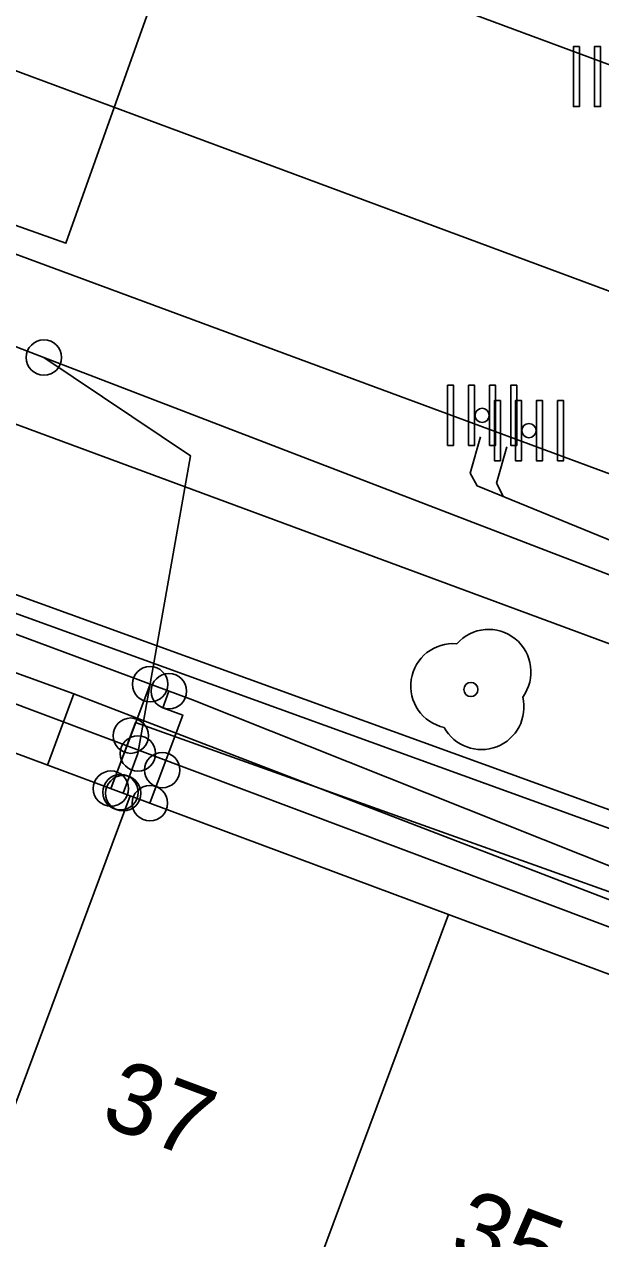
# Model space of a CAD drawing. Extents: x 192672 to 192910, y 446344 to 446512.
# Drawn here: x 192717.1 to 192725.25, y 446389.57 to 446406.75 of the extents above; entities that cross this region are included whole.
import ezdxf

# ---------------------------------------------------------------- set-up
doc = ezdxf.new("R2010")
doc.units = 0
for name, color, linetype in [('B-OI-KL-BUISLEIDING_OLIEGASCHEMICALIEN_GASLAGEDRUK-G', 7, 'Continuous'), ('B-OI-KL-DATA-G', 7, 'Continuous'), ('B-OI-KL-DATA_GTWP-S', 7, 'Continuous'), ('B-OI-KL-DATA_KABELBED-G', 7, 'Continuous'), ('B-OI-KL-DATA_MOF-S', 7, 'Continuous'), ('B-OI-KL-ET_LS-G', 7, 'Continuous'), ('B-OI-KL-ET_LS_DELIVERYPOINT-S', 7, 'Continuous'), ('B-OI-KL-GAS_LD_AFTAKZADEL-S', 7, 'Continuous'), ('B-OI-KL-GAS_LD_DELIVERYPOINT-S', 7, 'Continuous'), ('B-OI-KL-GAS_LD_OVERGANGSSTUK-S', 7, 'Continuous'), ('B-OI-KL-WATER-G', 7, 'Continuous'), ('B-OI-RI-RIOOLVRIJVERVAL-G', 7, 'Continuous'), ('boom', 7, 'Continuous'), ('Default', 7, 'Continuous'), ('huisnummerreeks BGT', 7, 'Continuous'), ('kant open verharding', 7, 'Continuous'), ('kant verharding', 7, 'Continuous'), ('kolk', 7, 'Continuous'), ('pand op maaiveld vlak', 7, 'Continuous'), ('verkeerseiland - berm', 7, 'Continuous')]:
    doc.layers.add(name, color=color, linetype=linetype)

# ---------------------------------------------------------------- blocks, each defined once
blk = doc.blocks.new('B-OI-KL-GAS_LD_AFTAKZADEL-S')
at = {"layer": 'Default'}
blk.add_circle((0, 0), 0.25, dxfattribs=at)
blk = doc.blocks.new('B-OI-KL-GAS_LD_DELIVERYPOINT-S')
at = {"layer": 'Default'}
blk.add_circle((0, 0), 0.25, dxfattribs=at)
blk = doc.blocks.new('B-OI-KL-GAS_LD_OVERGANGSSTUK-S')
at = {"layer": 'Default'}
blk.add_circle((0, 0), 0.25, dxfattribs=at)
blk = doc.blocks.new('B-OI-KL-ET_LS_DELIVERYPOINT-S')
at = {"layer": 'Default'}
blk.add_circle((0, 0), 0.25, dxfattribs=at)
blk = doc.blocks.new('B-OI-KL-DATA_GTWP-S')
at = {"layer": 'Default'}
blk.add_circle((0, 0), 0.25, dxfattribs=at)
blk = doc.blocks.new('B-OI-KL-DATA_MOF-S')
at = {"layer": 'Default'}
blk.add_circle((0, 0), 0.25, dxfattribs=at)

msp = doc.modelspace()

# ---------------------------------------------------------------- linework, layer by layer
at = {"layer": 'B-OI-KL-BUISLEIDING_OLIEGASCHEMICALIEN_GASLAGEDRUK-G'}
for points in [[(192709.208, 446401.012), (192719.482, 446397.193), (192733.825, 446391.479)], [(192718.883, 446397.416), (192718.609, 446396.688)], [(192719.149, 446397.317), (192719.062, 446397.082), (192719.344, 446396.978), (192719.055, 446396.202)], [(192718.609, 446396.688), (192718.329, 446395.939)], [(192719.055, 446396.202), (192718.88, 446395.733)]]:
    msp.add_lwpolyline(points, dxfattribs=at)
at = {"layer": 'B-OI-KL-DATA-G'}
for points in [[(192710.163, 446400.046), (192717.806, 446397.281)], [(192717.806, 446397.281), (192717.431, 446396.273)], [(192717.806, 446397.281), (192729.315, 446392.851), (192728.962, 446391.978)]]:
    msp.add_lwpolyline(points, dxfattribs=at)
at = {"layer": 'B-OI-KL-DATA_KABELBED-G'}
for points in [[(192733.82, 446395.718), (192726.444, 446398.553), (192717.381, 446402.036), (192715.981, 446402.574), (192711.535, 446404.244), (192702.923, 446407.477), (192692.564, 446411.367), (192684.205, 446414.506), (192682.207, 446415.256), (192682.206, 446415.257), (192675.743, 446417.684)], [(192717.381, 446402.036), (192719.453, 446400.646), (192718.711, 446396.436)], [(192718.711, 446396.436), (192718.502, 446395.874)]]:
    msp.add_lwpolyline(points, dxfattribs=at)
at = {"layer": 'B-OI-KL-ET_LS-G'}
for points in [[(192675.743, 446412.643), (192733.67, 446390.862), (192732.765, 446387.575)], [(192732.15, 446406.177), (192731.012, 446406.556), (192726.559, 446394.948), (192704.717, 446402.86), (192705.191, 446404.234), (192705.001, 446404.897)]]:
    msp.add_lwpolyline(points, dxfattribs=at)
at = {"layer": 'B-OI-KL-WATER-G'}
msp.add_lwpolyline([(192733.144, 446391.701), (192732.91, 446391.789), (192718.678, 446396.876), (192718.329, 446395.938)], dxfattribs=at)
at = {"layer": 'B-OI-RI-RIOOLVRIJVERVAL-G'}
for points in [[(192716.55, 446406.25), (192740.63, 446397.31)], [(192725.716, 446399.317), (192723.505, 446400.22), (192723.406, 446400.4), (192723.553, 446400.913)], [(192723.78, 446400.26), (192723.927, 446400.772)], [(192723.878, 446400.068), (192723.78, 446400.26)]]:
    msp.add_lwpolyline(points, dxfattribs=at)
at = {"layer": 'boom'}
msp.add_circle((192723.418, 446397.341), 0.1, dxfattribs=at)
for centre, radius, start, end in [((192723.668, 446397.591), 0.6, 323.5446, 138.4658), ((192723.168, 446397.391), 0.6, 85.137, 257.7544), ((192723.418, 446397.341), 0.1, 0, 180), ((192723.418, 446397.341), 0.1, 180, 0), ((192723.568, 446397.091), 0.6, 208.5058, 13.8356)]:
    msp.add_arc(centre, radius, start, end, dxfattribs=at)
at = {"layer": 'kant open verharding'}
msp.add_lwpolyline([(192719.251, 446408.036), (192715.613, 446409.33), (192714.055, 446404.947), (192717.693, 446403.653), (192719.251, 446408.036)], dxfattribs=at)
at = {"layer": 'kant verharding'}
for p, q in [((192675.743, 446424.623), (192733.082, 446403.313)), ((192675.743, 446418.762), (192731.114, 446398.266))]:
    msp.add_line(p, q, dxfattribs=at)
at = {"layer": 'kolk'}
for points in [[(192724.953, 446406.009), (192724.953, 446406.434), (192724.868, 446406.434), (192724.868, 446406.009), (192724.868, 446405.584), (192724.953, 446405.584)], [(192725.251, 446406.009), (192725.251, 446406.434), (192725.166, 446406.434), (192725.166, 446406.009), (192725.166, 446405.584), (192725.251, 446405.584)], [(192723.173, 446401.218), (192723.173, 446401.643), (192723.088, 446401.643), (192723.088, 446401.218), (192723.088, 446400.793), (192723.173, 446400.793)], [(192723.471, 446401.218), (192723.471, 446401.643), (192723.386, 446401.643), (192723.386, 446401.218), (192723.386, 446400.793), (192723.471, 446400.793)], [(192723.768, 446401.218), (192723.768, 446401.643), (192723.683, 446401.643), (192723.683, 446401.218), (192723.683, 446400.793), (192723.768, 446400.793)], [(192724.066, 446401.218), (192724.066, 446401.643), (192723.981, 446401.643), (192723.981, 446401.218), (192723.981, 446400.793), (192724.066, 446400.793)], [(192723.836, 446401.002), (192723.836, 446401.427), (192723.751, 446401.427), (192723.751, 446401.002), (192723.751, 446400.577), (192723.836, 446400.577)], [(192724.134, 446401.002), (192724.134, 446401.427), (192724.049, 446401.427), (192724.049, 446401.002), (192724.049, 446400.577), (192724.134, 446400.577)], [(192724.431, 446401.002), (192724.431, 446401.427), (192724.346, 446401.427), (192724.346, 446401.002), (192724.346, 446400.577), (192724.431, 446400.577)], [(192724.729, 446401.002), (192724.729, 446401.427), (192724.644, 446401.427), (192724.644, 446401.002), (192724.644, 446400.577), (192724.729, 446400.577)]]:
    msp.add_lwpolyline(points, close=True, dxfattribs=at)
for centre, start, end in [((192723.577, 446401.218), 0, 180), ((192723.577, 446401.218), 180, 0), ((192724.24, 446401.002), 0, 180), ((192724.24, 446401.002), 180, 0)]:
    msp.add_arc(centre, 0.1, start, end, dxfattribs=at)
at = {"layer": 'pand op maaiveld vlak'}
for p, q in [((192714.097, 446397.514), (192718.599, 446395.838)), ((192715.962, 446388.755), (192718.599, 446395.838)), ((192723.101, 446394.161), (192718.599, 446395.838)), ((192727.603, 446392.484), (192723.101, 446394.161))]:
    msp.add_line(p, q, dxfattribs=at)
msp.add_lwpolyline([(192721.407, 446386.724), (192720.462, 446387.076), (192723.101, 446394.161)], dxfattribs=at)
at = {"layer": 'verkeerseiland - berm'}
msp.add_line((192726.814, 446397.454), (192715.622, 446401.596), dxfattribs=at)
msp.add_lwpolyline([(192726.814, 446397.454), (192726.067, 446395.39), (192714.846, 446399.456), (192715.622, 446401.596)], dxfattribs=at)

# ---------------------------------------------------------------- block references
at = {"layer": 'B-OI-KL-DATA_GTWP-S'}
for p in [(192717.381, 446402.036), (192718.711, 446396.436), (192718.711, 446396.436), (192718.502, 446395.874)]:
    msp.add_blockref('B-OI-KL-DATA_GTWP-S', p, dxfattribs=at)
at = {"layer": 'B-OI-KL-DATA_MOF-S'}
for p in [(192717.381, 446402.036), (192718.711, 446396.436)]:
    msp.add_blockref('B-OI-KL-DATA_MOF-S', p, dxfattribs=at)
at = {"layer": 'B-OI-KL-ET_LS_DELIVERYPOINT-S'}
msp.add_blockref('B-OI-KL-ET_LS_DELIVERYPOINT-S', (192718.464, 446395.888), dxfattribs=at)
at = {"layer": 'B-OI-KL-GAS_LD_AFTAKZADEL-S'}
for p in [(192718.883, 446397.416), (192719.149, 446397.317)]:
    msp.add_blockref('B-OI-KL-GAS_LD_AFTAKZADEL-S', p, dxfattribs=at)
at = {"layer": 'B-OI-KL-GAS_LD_DELIVERYPOINT-S'}
for p in [(192718.329, 446395.939), (192718.88, 446395.733)]:
    msp.add_blockref('B-OI-KL-GAS_LD_DELIVERYPOINT-S', p, dxfattribs=at)
at = {"layer": 'B-OI-KL-GAS_LD_OVERGANGSSTUK-S'}
for p in [(192718.609, 446396.688), (192719.055, 446396.202)]:
    msp.add_blockref('B-OI-KL-GAS_LD_OVERGANGSSTUK-S', p, dxfattribs=at)

# ---------------------------------------------------------------- texts
at = {"layer": 'huisnummerreeks BGT'}
for s, p in [('37', (192718.152, 446391.203)), ('35', (192723.079, 446389.367))]:
    msp.add_text(s, height=1, rotation=339.6, dxfattribs=at).set_placement(p)

doc.saveas('drawing.dxf')
